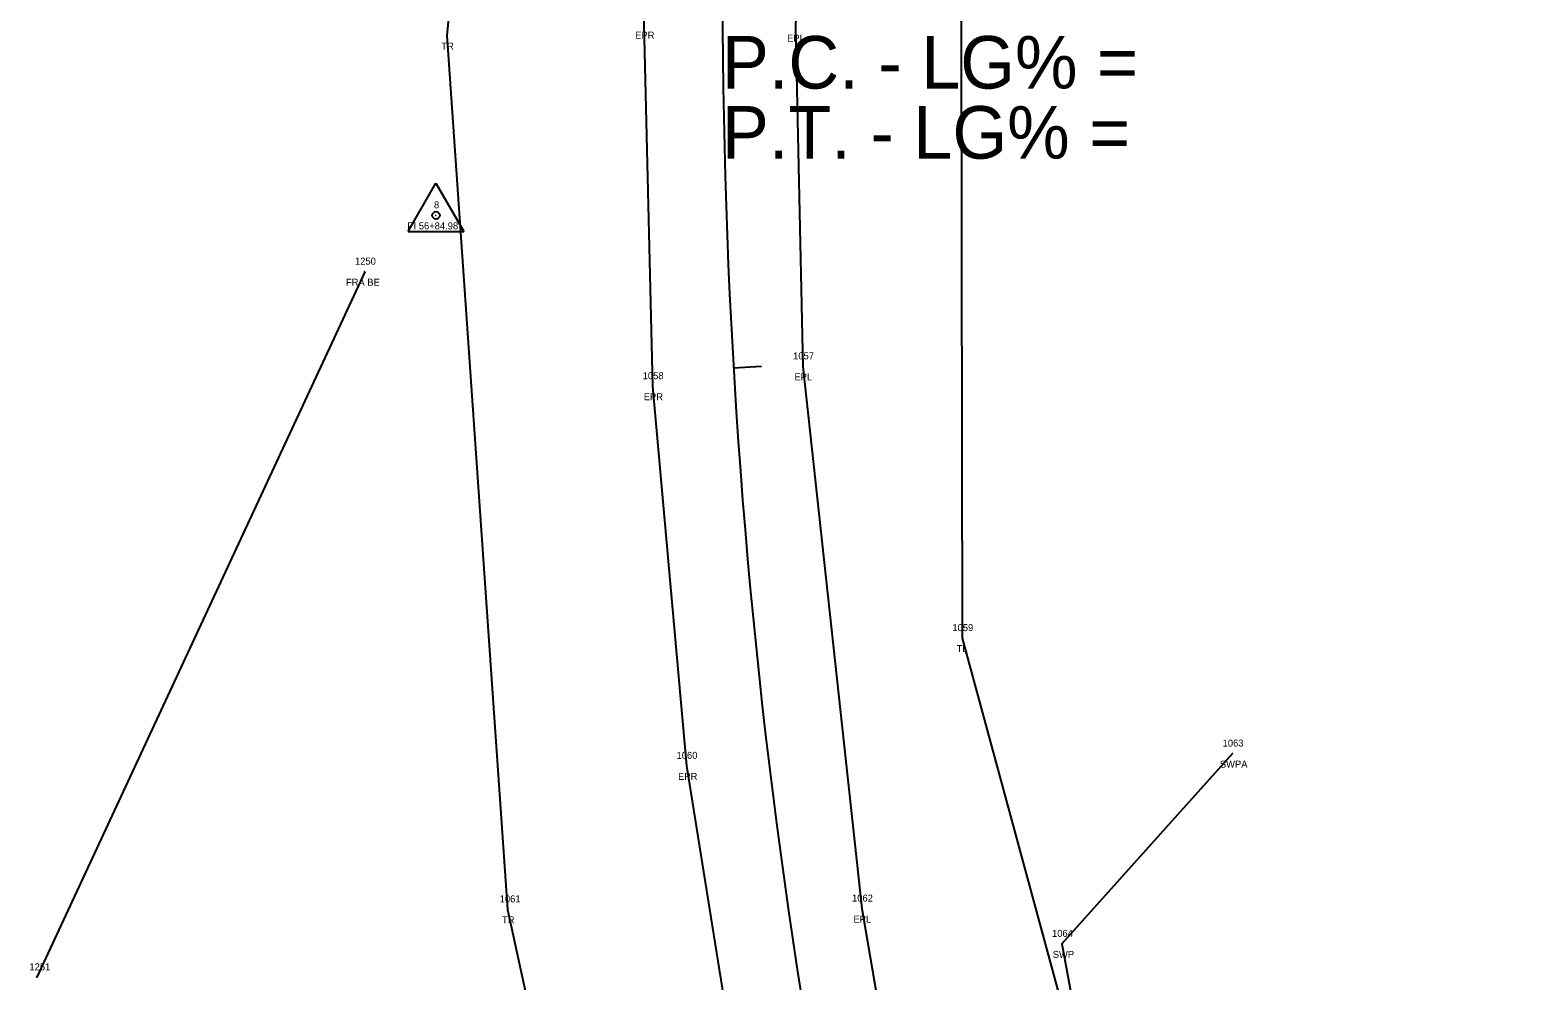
# Model space of a CAD drawing. Extents: x 2432632 to 2433497, y 684847 to 688233.
# Drawn here: x 2432826.3 to 2433041.4, y 687022.7 to 687158.3 of the extents above; entities that cross this region are included whole.
import ezdxf

# ---------------------------------------------------------------- set-up
doc = ezdxf.new("R2010")
doc.units = 0
for name, color, linetype in [('RD_EX_Fence_Other', 7, 'Continuous'), ('RD_EX_Fence_Other_txCode', 7, 'Continuous'), ('RD_EX_H2O', 7, 'Continuous'), ('RD_EX_H2O_txCode', 7, 'Continuous'), ('RD_EX_Road', 7, 'Continuous'), ('RD_EX_Road_txCode', 7, 'Continuous'), ('RD_EX_VEG', 7, 'Continuous'), ('RD_EX_VEG_txCode', 7, 'Continuous'), ('RD_HC_Cl', 7, 'Continuous'), ('RD_HC_Data', 7, 'Continuous'), ('RD_HC_Data_Tic', 7, 'Continuous'), ('RD_HC_txCode', 7, 'Continuous'), ('RD_SMD_Locator', 7, 'Continuous')]:
    doc.layers.add(name, color=color, linetype=linetype)

msp = doc.modelspace()

# ---------------------------------------------------------------- linework, layer by layer
at = {"layer": 'RD_EX_Fence_Other'}
msp.add_line((2432874.05, 687123.88), (2432827.3, 687023.24), dxfattribs=at)
at = {"layer": 'RD_EX_H2O'}
msp.add_lwpolyline([(2432997.82, 687055.15), (2432973.49, 687028.01), (2432977.67, 687005.43), (2432993.65, 686937.13), (2433002.95, 686914.83), (2433036.11, 686913.46)], dxfattribs=at)
at = {"layer": 'RD_EX_Road'}
for points in [[(2433130.63, 688090.22), (2433103.18, 687988.73), (2433075.68, 687887.89), (2433049.83, 687790.75), (2433022.33, 687689.17), (2432994.76, 687586.82), (2432966.23, 687480.17), (2432943.15, 687390.42), (2432931.4, 687334.3), (2432921.83, 687273.88), (2432915.64, 687215.4), (2432913.86, 687159.12), (2432915.08, 687107.55), (2432919.97, 687053.4), (2432928.7, 686998.89), (2432946.77, 686924.59), (2432964.57, 686864), (2432997.3, 686766.34), (2433031.44, 686666.38), (2433066.06, 686565.78), (2433098.73, 686469.74)], [(2432986.34, 687474.01), (2432964, 687384.38), (2432952.4, 687330.76), (2432943.09, 687273.42), (2432937.12, 687213.43), (2432935.51, 687158.7), (2432936.54, 687110.38), (2432944.97, 687033.04), (2432950.24, 687002.26), (2432966.49, 686930.23), (2432984.9, 686870.1)]]:
    msp.add_lwpolyline(points, dxfattribs=at)
at = {"layer": 'RD_EX_VEG'}
for points in [[(2433112.43, 688094.61), (2433041.17, 687898.89), (2432988.9, 687699.78), (2432947.96, 687578.08), (2432935.9, 687556.87), (2432944.3, 687538.7), (2432913.88, 687397.98), (2432902.4, 687330.02), (2432885.78, 687157.56), (2432894.43, 687032.93), (2432918.07, 686924.4), (2432974.73, 686759.54), (2433073.82, 686456.42), (2433099.9, 686365.23), (2433115.47, 686257.21), (2433114.64, 686158.77), (2433095.68, 686092.78)], [(2433166.25, 688082.87), (2433111.93, 687876.69), (2433067.75, 687703.46), (2433065.05, 687678.03), (2433052.74, 687645.62), (2433005.45, 687469.88), (2432979.96, 687326.61), (2432966.8, 687267.34), (2432959.05, 687210.65), (2432959.25, 687071.62), (2432974.82, 687014.37), (2432998.13, 686938.9), (2433012.99, 686878.7), (2433054.45, 686782.35), (2433123.54, 686586.06), (2433129.82, 686546.35), (2433158.34, 686434.26), (2433192.79, 686274.67), (2433189.42, 686162.6), (2433197.4, 686074.41)]]:
    msp.add_lwpolyline(points, dxfattribs=at)
at = {"layer": 'RD_HC_Cl'}
msp.add_arc((2433840.56, 687163.67), 915.47, 164.98581, 198.81644, dxfattribs=at)
at = {"layer": 'RD_HC_Data'}
for p, q in [((2432880.25, 687129.63), (2432884.22, 687136.51)), ((2432884.22, 687136.51), (2432888.19, 687129.63)), ((2432880.25, 687129.63), (2432888.19, 687129.63))]:
    msp.add_line(p, q, dxfattribs=at)
msp.add_circle((2432884.22, 687131.92), 0.529, dxfattribs=at)
at = {"layer": 'RD_HC_Data_Tic'}
msp.add_line((2432926.65, 687110.16), (2432930.65, 687110.4), dxfattribs=at)
at = {"layer": 'RD_SMD_Locator'}
for centre in [(2432885.78, 687157.56), (2432884.22, 687131.92), (2432874.05, 687123.88), (2432936.54, 687110.38), (2432915.08, 687107.55), (2432959.25, 687071.62), (2432997.82, 687055.15), (2432919.97, 687053.4), (2432894.43, 687032.93), (2432944.97, 687033.04), (2432973.49, 687028.01), (2432827.3, 687023.24)]:
    msp.add_circle(centre, 0.001, dxfattribs=at)

# ---------------------------------------------------------------- texts
at = {"layer": 'RD_EX_Fence_Other_txCode'}
for s, p in [('1250', (2432872.67, 687124.88)), ('FRA BE', (2432871.38, 687121.88)), ('1251', (2432826.24, 687024.24))]:
    msp.add_text(s, height=1, dxfattribs=at).set_placement(p)
at = {"layer": 'RD_EX_H2O_txCode'}
for s, p in [('1063', (2432996.41, 687056.15)), ('SWPA', (2432996.02, 687053.15)), ('1064', (2432972.08, 687029.01)), ('SWP', (2432972.18, 687026.01))]:
    msp.add_text(s, height=1, dxfattribs=at).set_placement(p)
at = {"layer": 'RD_EX_Road_txCode'}
for s, p in [('EPR', (2432912.63, 687157.12)), ('EPL', (2432934.3, 687156.7)), ('1057', (2432935.15, 687111.38)), ('1058', (2432913.7, 687108.55)), ('EPL', (2432935.34, 687108.38)), ('EPR', (2432913.85, 687105.55)), ('1060', (2432918.53, 687054.4)), ('EPR', (2432918.75, 687051.4)), ('1062', (2432943.56, 687034.04)), ('EPL', (2432943.76, 687031.04))]:
    msp.add_text(s, height=1, dxfattribs=at).set_placement(p)
at = {"layer": 'RD_EX_VEG_txCode'}
for s, p in [('TR', (2432884.99, 687155.56)), ('1059', (2432957.87, 687072.62)), ('TL', (2432958.48, 687069.62)), ('1061', (2432893.31, 687033.93)), ('TR', (2432893.64, 687030.93))]:
    msp.add_text(s, height=1, dxfattribs=at).set_placement(p)
at = {"layer": 'RD_HC_Data'}
for s, p in [('P.C. - LG% = ', (2432925, 687150)), ('P.T. - LG% = ', (2432925, 687140))]:
    msp.add_text(s, height=7.5, dxfattribs=at).set_placement(p)
at = {"layer": 'RD_HC_txCode'}
for s, p in [('8', (2432883.93, 687132.92)), ('PI 56+84.98', (2432880.13, 687129.92))]:
    msp.add_text(s, height=1, dxfattribs=at).set_placement(p)

doc.saveas('drawing.dxf')
